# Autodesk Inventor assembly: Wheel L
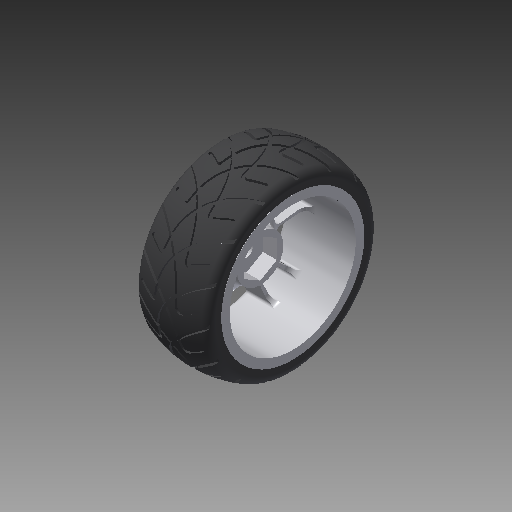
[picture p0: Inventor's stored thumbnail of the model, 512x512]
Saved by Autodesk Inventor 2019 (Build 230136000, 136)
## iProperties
Shininess: 50.0
Length Units: 11272
Angle Units: 11279
Time Units: 11290
Mass Units: 11286
Length Display Precision: 4
Angle Display Precision: 2
Compacted: True
Company: Autodesk
Created: 2000-05
Part Number: Wheel L
Project: Inventor Samples
User Status: IN PROGRESS
Description: ASSEMBLY - WHEEL (LEFT)
Document SubType Name: Assembly
Designer: The PD Team
Mass: 35.0352 g
Surface Area: 335.101 cm^2
Volume: 19.2965 cm^3
Density: 1.81563 g/cm^3
Density: 0.0
Volumn: 0.0
Area: 0.0
PropertySet Name: Model Information
Control State: 0
Master: False
Checked Out: False
Checked Out Date: 2018-05-30
Last Check In Date: 2018-05-30
Author: The PD Team
Revision Number: A
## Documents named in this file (3)
- C:\Users\itools\Desktop\autodesk_inventor_2018_samples\Models\Assemblies\Suspension\Components\Wheel L.iam
- C:\Users\itools\Desktop\autodesk_inventor_2018_samples\Models\Assemblies\Suspension\Components\Wheel.ipt
- C:\Users\itools\Desktop\autodesk_inventor_2018_samples\Models\Assemblies\Suspension\Components\Tire - 2.ipt
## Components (2 placed, 2 different names)
1. Wheel:1 — Insert:1
2. Tire - 2:1 — Insert:1
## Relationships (1: Insert 1)
- Insert:1: Wheel:1 ↔ Tire - 2:1
